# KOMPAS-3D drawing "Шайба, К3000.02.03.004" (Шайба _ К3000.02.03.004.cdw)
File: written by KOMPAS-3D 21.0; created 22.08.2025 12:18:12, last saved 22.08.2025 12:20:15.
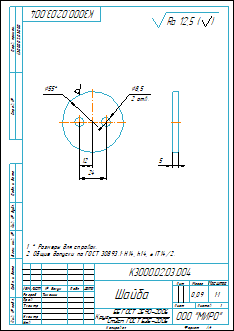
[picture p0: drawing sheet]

Sheet 1: A4, portrait

Document properties: Автор: Lutik; Знак неуказанной шероховатости: 4; Параметр неуказанной шероховатости: Ra 12,5; Масса: 0.088797

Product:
- Part/product: Шайба  | designation К3000.02.03.004
    Материал: Круг$d55 ГОСТ 2590-2006;Ст3сп ГОСТ 535-2005$ (density 7850 kg/m3)
    Масса: 0.088797
    Форматы листов документа: A4

Title block, sheet 1: Наименование: Шайба; designation: К3000.02.03.004; Материал: Круг 55 ГОСТ 2590-2006 Ст3сп ГОСТ 535-2005; Масса: 0,09; Количество листов документа: 1; organisation: ООО "МИРО"; Форматы листов документа: A4; stored path: C:\Users\Lutik\YandexDisk\Документы\Новая папка\Бабка задняя\2D\Опора_К3000.02.03.000\Шайба _ К3000.02.03.004.cdw; Разработал: Тимонин

Views: Вид 1, Слева, Проекционный вид 2
Referenced files in C:\Users\Lutik\YandexDisk\Документы\Новая папка\Бабка задняя\3D\: Шайба_29.m3d
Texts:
  Ra 12,5
  Ra 12,5 ( )
  К3000.02.03.004 Шайба
Dimensions and other numbers on the sheet: 55; 12; 24; 8,5; 2 отв.; 5; 1:1; 1; 0,09

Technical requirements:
  * Размеры для справок.
  Общие допуски по ГОСТ 30893.1: Н14, h14, ± IT14/2.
